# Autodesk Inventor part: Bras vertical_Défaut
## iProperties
Shininess: 64.0
Length Units: 11269
Angle Units: 11279
Time Units: 11290
Mass Units: 11283
Length Display Precision: 3
Angle Display Precision: 2
Compacted: True
Part Number: Bras vertical_Défaut
Document SubType Name: Modeling
Created: 2006-11
Material: Par défaut
Designer: profs_sti
Density: 0.0
Volumn: 0.0
Area: 0.0
PropertySet Name: Model Information
Control State: 0
Master: False
Checked Out: False
Author: profs_sti
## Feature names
1. Base1
